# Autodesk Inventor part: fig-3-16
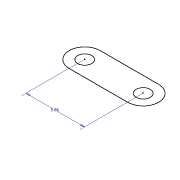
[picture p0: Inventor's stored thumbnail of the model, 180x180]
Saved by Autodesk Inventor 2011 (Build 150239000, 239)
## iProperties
Created: 2009-11
Part Number: fig-3-16
Document SubType Name: Modeling
Designer: Sham
Density: 1 g/cm^3
Author: Sham
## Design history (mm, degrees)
sketch "Sketch1"
  geometry: L1 (4.59, -0.041)-(10.25, -0.041); L2 (4.59, -3.041)-(10.25, -3.041); C1 r 0.679 at (4.59, -1.541); C2 r 0.679 at (10.25, -1.541); A1 r 1.5 centre (4.59, -1.541) between (4.59, -0.041) and (4.59, -3.041); A2 r 1.5 centre (10.25, -1.541) between (10.25, -3.041) and (10.25, -0.041)
  constraints: 4 centre point, 4 end point, 4 point on circle, 2 coincident, 2 horizontal, 2 tangent, 1 equal radius
  dimensions: "d2" = 5.66 dimension on A1.centre A1 A2.centre A2 L1.start L1.end L1 L2.start L2.end L2 C1.centre C1 C2.centre C2; "d2" = 5.66 distance of A2.centre A1.centre
